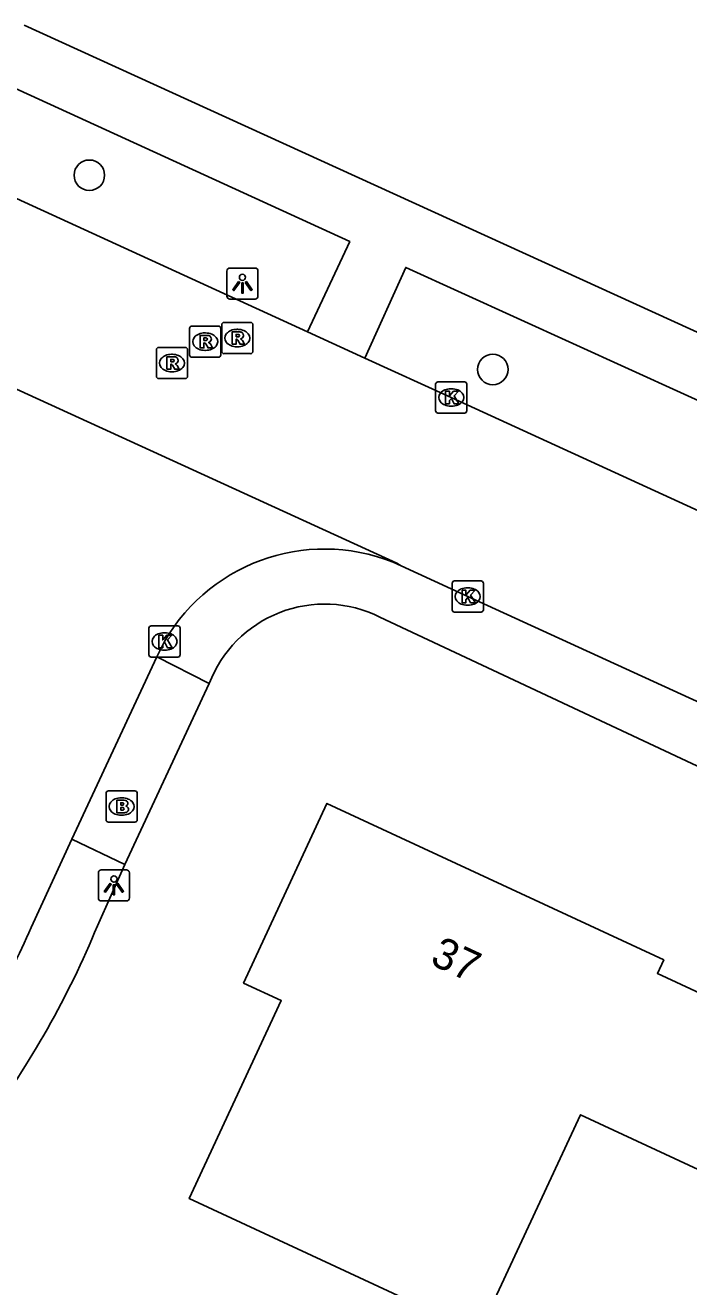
# Model space of a CAD drawing. Extents: x 162722 to 165099, y 384721 to 386283.
# Drawn here: x 164039.98 to 164061.27, y 385139.03 to 385179.48 of the extents above; entities that cross this region are included whole.
import ezdxf

# ---------------------------------------------------------------- set-up
doc = ezdxf.new("R2010")
doc.units = 0
for name, color, linetype in [('IMGEO_Boom', 7, 'Continuous'), ('IMGEO_Brandkraan', 7, 'Continuous'), ('IMGEO_Kolk', 7, 'Continuous'), ('IMGEO_Lichtpunt', 7, 'Continuous'), ('IMGEO_Pand', 7, 'Continuous'), ('IMGEO_Pand_nummerreeks', 7, 'Continuous'), ('IMGEO_Parkeervlak_open', 7, 'Continuous'), ('IMGEO_Rijbaan_lokaal_gesloten', 7, 'Continuous'), ('IMGEO_Rioolput', 7, 'Continuous'), ('IMGEO_Voetpad_open', 7, 'Continuous')]:
    doc.layers.add(name, color=color, linetype=linetype)

msp = doc.modelspace()

# ---------------------------------------------------------------- linework, layer by layer
at = {"layer": 'IMGEO_Boom'}
for centre in [(164042.041, 385174.672), (164054.98, 385168.446)]:
    msp.add_circle(centre, 0.489, dxfattribs=at)
at = {"layer": 'IMGEO_Brandkraan'}
for p, q in [((164042.576, 385154.006), (164042.576, 385154.858)), ((164042.651, 385154.932), (164043.503, 385154.932)), ((164043.577, 385154.858), (164043.577, 385154.006)), ((164043.064, 385154.712), (164043.089, 385154.712)), ((164043.503, 385153.932), (164042.651, 385153.932)), ((164043.087, 385154.152), (164043.062, 385154.152))]:
    msp.add_line(p, q, dxfattribs=at)
for points in [[(164042.576, 385154.006), (164042.576, 385154.858)], [(164042.651, 385154.932), (164043.503, 385154.932)], [(164043.577, 385154.858), (164043.577, 385154.006)], [(164042.924, 385154.632), (164042.924, 385154.232), (164043.137, 385154.232)], [(164043.155, 385154.632), (164042.924, 385154.632)], [(164043.103, 385154.551), (164043.049, 385154.551), (164043.049, 385154.475)], [(164043.049, 385154.475), (164043.102, 385154.475)], [(164043.111, 385154.399), (164043.049, 385154.399), (164043.049, 385154.318)], [(164043.503, 385153.932), (164042.651, 385153.932)], [(164043.049, 385154.318), (164043.111, 385154.318)]]:
    msp.add_lwpolyline(points, dxfattribs=at)
for centre, radius, start, end in [((164042.653, 385154.856), 0.0765, 91.552, 178.448), ((164042.653, 385154.856), 0.0765, 91.552, 178.448), ((164043.501, 385154.856), 0.0765, 1.552, 88.448), ((164043.501, 385154.856), 0.0765, 1.552, 88.448), ((164043.104, 385154.513), 0.0379, 267.8285, 90.9355), ((164043.112, 385154.358), 0.0404, 269.8759, 90.5077), ((164043.159, 385154.487), 0.145, 59.4692, 91.5367), ((164043.184, 385154.534), 0.0922, 285.5137, 58.1501), ((164043.189, 385154.342), 0.105, 301.3115, 78.989), ((164042.653, 385154.008), 0.0765, 181.552, 268.448), ((164042.653, 385154.008), 0.0765, 181.552, 268.448), ((164043.143, 385154.483), 0.251, 268.6676, 293.5347), ((164043.501, 385154.008), 0.0765, 271.552, 358.448), ((164043.501, 385154.008), 0.0765, 271.552, 358.448)]:
    msp.add_arc(centre, radius, start, end, dxfattribs=at)
for centre, major_axis, ratio, start_param, end_param in [((164043.063, 385154.432), (-0.387, 0.002), 0.722429, 4.712389, 7.853982), ((164043.088, 385154.432), (-0.39, 0.002), 0.717154, 1.570796, 4.712389)]:
    msp.add_ellipse(centre, major_axis=major_axis, ratio=ratio, start_param=start_param, end_param=end_param, dxfattribs=at)
at = {"layer": 'IMGEO_Kolk'}
for p, q in [((164053.147, 385167.122), (164053.147, 385167.974)), ((164053.222, 385168.048), (164054.074, 385168.048)), ((164053.635, 385167.828), (164053.66, 385167.828)), ((164054.148, 385167.974), (164054.148, 385167.122)), ((164054.074, 385167.048), (164053.222, 385167.048)), ((164053.658, 385167.268), (164053.633, 385167.268)), ((164053.751, 385161.665), (164054.603, 385161.665)), ((164053.676, 385160.739), (164053.676, 385161.591)), ((164054.164, 385161.445), (164054.189, 385161.445)), ((164054.677, 385161.591), (164054.677, 385160.739)), ((164054.187, 385160.885), (164054.162, 385160.885)), ((164054.603, 385160.665), (164053.751, 385160.665)), ((164043.951, 385159.299), (164043.951, 385160.151)), ((164044.026, 385160.225), (164044.878, 385160.225)), ((164044.439, 385160.005), (164044.464, 385160.005)), ((164044.952, 385160.151), (164044.952, 385159.299)), ((164044.878, 385159.225), (164044.026, 385159.225)), ((164044.462, 385159.445), (164044.437, 385159.445))]:
    msp.add_line(p, q, dxfattribs=at)
for points in [[(164053.147, 385167.122), (164053.147, 385167.974)], [(164053.222, 385168.048), (164054.074, 385168.048)], [(164053.468, 385167.748), (164053.591, 385167.748), (164053.591, 385167.597), (164053.721, 385167.748), (164053.885, 385167.748), (164053.739, 385167.597), (164053.892, 385167.348), (164053.74, 385167.348), (164053.655, 385167.512), (164053.591, 385167.445), (164053.591, 385167.348), (164053.468, 385167.348), (164053.468, 385167.748)], [(164054.148, 385167.974), (164054.148, 385167.122)], [(164054.074, 385167.048), (164053.222, 385167.048)], [(164053.751, 385161.665), (164054.603, 385161.665)], [(164053.676, 385160.739), (164053.676, 385161.591)], [(164053.997, 385161.365), (164054.12, 385161.365), (164054.12, 385161.214), (164054.25, 385161.365), (164054.414, 385161.365), (164054.268, 385161.214), (164054.421, 385160.965), (164054.269, 385160.965), (164054.184, 385161.129), (164054.12, 385161.062), (164054.12, 385160.965), (164053.997, 385160.965), (164053.997, 385161.365)], [(164054.677, 385161.591), (164054.677, 385160.739)], [(164054.603, 385160.665), (164053.751, 385160.665)], [(164043.951, 385159.299), (164043.951, 385160.151)], [(164044.026, 385160.225), (164044.878, 385160.225)], [(164044.952, 385160.151), (164044.952, 385159.299)], [(164044.272, 385159.925), (164044.395, 385159.925), (164044.395, 385159.774), (164044.525, 385159.925), (164044.689, 385159.925), (164044.543, 385159.774), (164044.696, 385159.525), (164044.544, 385159.525), (164044.459, 385159.689), (164044.395, 385159.622), (164044.395, 385159.525), (164044.272, 385159.525), (164044.272, 385159.925)], [(164044.878, 385159.225), (164044.026, 385159.225)]]:
    msp.add_lwpolyline(points, dxfattribs=at)
for centre, start, end in [((164053.224, 385167.972), 91.552, 178.448), ((164053.224, 385167.972), 91.552, 178.448), ((164054.072, 385167.972), 1.552, 88.448), ((164054.072, 385167.972), 1.552, 88.448), ((164053.224, 385167.124), 181.552, 268.448), ((164053.224, 385167.124), 181.552, 268.448), ((164054.072, 385167.124), 271.552, 358.448), ((164054.072, 385167.124), 271.552, 358.448), ((164053.753, 385161.589), 91.552, 178.448), ((164053.753, 385161.589), 91.552, 178.448), ((164054.601, 385161.589), 1.552, 88.448), ((164054.601, 385161.589), 1.552, 88.448), ((164053.753, 385160.741), 181.552, 268.448), ((164053.753, 385160.741), 181.552, 268.448), ((164054.601, 385160.741), 271.552, 358.448), ((164054.601, 385160.741), 271.552, 358.448), ((164044.028, 385160.149), 91.552, 178.448), ((164044.028, 385160.149), 91.552, 178.448), ((164044.876, 385160.149), 1.552, 88.448), ((164044.876, 385160.149), 1.552, 88.448), ((164044.028, 385159.301), 181.552, 268.448), ((164044.028, 385159.301), 181.552, 268.448), ((164044.876, 385159.301), 271.552, 358.448), ((164044.876, 385159.301), 271.552, 358.448)]:
    msp.add_arc(centre, 0.0765, start, end, dxfattribs=at)
for centre, major_axis, ratio, start_param, end_param in [((164053.634, 385167.548), (-0.387, 0.002), 0.722429, 4.712389, 7.853982), ((164053.659, 385167.548), (-0.39, 0.002), 0.717154, 1.570796, 4.712389), ((164054.163, 385161.165), (-0.387, 0.002), 0.722429, 4.712389, 7.853982), ((164054.188, 385161.165), (-0.39, 0.002), 0.717154, 1.570796, 4.712389), ((164044.438, 385159.725), (-0.387, 0.002), 0.722429, 4.712389, 7.853982), ((164044.463, 385159.725), (-0.39, 0.002), 0.717154, 1.570796, 4.712389)]:
    msp.add_ellipse(centre, major_axis=major_axis, ratio=ratio, start_param=start_param, end_param=end_param, dxfattribs=at)
at = {"layer": 'IMGEO_Lichtpunt'}
for p, q in [((164046.452, 385171.602), (164046.452, 385170.795)), ((164046.452, 385171.602), (164046.452, 385170.795)), ((164047.354, 385171.697), (164046.546, 385171.697)), ((164047.354, 385171.697), (164046.546, 385171.697)), ((164047.448, 385170.795), (164047.448, 385171.602)), ((164047.448, 385170.795), (164047.448, 385171.602)), ((164046.546, 385170.701), (164047.354, 385170.701)), ((164046.546, 385170.701), (164047.354, 385170.701)), ((164042.329, 385152.308), (164042.329, 385151.501)), ((164042.329, 385152.308), (164042.329, 385151.501)), ((164043.231, 385152.403), (164042.423, 385152.403)), ((164043.231, 385152.403), (164042.423, 385152.403)), ((164043.325, 385151.501), (164043.325, 385152.308)), ((164043.325, 385151.501), (164043.325, 385152.308)), ((164042.423, 385151.407), (164043.231, 385151.407)), ((164042.423, 385151.407), (164043.231, 385151.407))]:
    msp.add_line(p, q, dxfattribs=at)
for points in [[(164046.826, 385171.266), (164046.865, 385171.238), (164046.677, 385170.976), (164046.639, 385171.003), (164046.826, 385171.266)], [(164046.928, 385171.218), (164046.975, 385171.218), (164046.975, 385170.896), (164046.928, 385170.896), (164046.928, 385171.218)], [(164047.038, 385171.238), (164047.076, 385171.265), (164047.263, 385171.003), (164047.224, 385170.975), (164047.038, 385171.238)], [(164042.703, 385151.972), (164042.742, 385151.944), (164042.554, 385151.682), (164042.516, 385151.709), (164042.703, 385151.972)], [(164042.805, 385151.924), (164042.852, 385151.924), (164042.852, 385151.602), (164042.805, 385151.602), (164042.805, 385151.924)], [(164042.915, 385151.944), (164042.953, 385151.971), (164043.14, 385151.709), (164043.101, 385151.681), (164042.915, 385151.944)]]:
    msp.add_lwpolyline(points, dxfattribs=at)
for centre in [(164046.951, 385171.4), (164042.828, 385152.106)]:
    msp.add_circle(centre, 0.0994, dxfattribs=at)
for centre, start, end in [((164046.546, 385171.602), 90, 180), ((164046.546, 385171.602), 90, 180), ((164047.354, 385171.602), 0, 90), ((164047.354, 385171.602), 0, 90), ((164046.546, 385170.795), 180, 270), ((164046.546, 385170.795), 180, 270), ((164047.354, 385170.795), 270, 0), ((164047.354, 385170.795), 270, 360), ((164042.423, 385152.308), 90, 180), ((164042.423, 385152.308), 90, 180), ((164043.231, 385152.308), 0, 90), ((164043.231, 385152.308), 0, 90), ((164042.423, 385151.501), 180, 270), ((164042.423, 385151.501), 180, 270), ((164043.231, 385151.501), 270, 0), ((164043.231, 385151.501), 270, 360)]:
    msp.add_arc(centre, 0.0946, start, end, dxfattribs=at)
at = {"layer": 'IMGEO_Pand'}
msp.add_lwpolyline([(164049.78, 385139.755), (164045.245, 385141.862), (164048.193, 385148.208), (164046.985, 385148.769), (164049.662, 385154.531), (164060.462, 385149.513), (164060.262, 385149.081), (164069.933, 385144.587), (164067.827, 385140.053), (164067.763, 385139.916), (164057.79, 385144.549), (164054.536, 385137.545), (164049.78, 385139.755)], dxfattribs=at)
at = {"layer": 'IMGEO_Parkeervlak_open'}
msp.add_lwpolyline([(164065.329, 385153.951), (164051.353, 385160.508)], dxfattribs=at)
msp.add_arc((164049.586, 385156.962), 3.962, 63.5124, 159.119, dxfattribs=at)
at = {"layer": 'IMGEO_Rijbaan_lokaal_gesloten'}
for points in [[(164049.034, 385169.655), (164038.924, 385174.279), (164037.91, 385174.757)], [(164050.878, 385168.812), (164049.034, 385169.655)], [(164052.042, 385162.153), (164051.9, 385162.23), (164036.795, 385169.137)], [(164070.499, 385159.839), (164069.537, 385160.271), (164053.648, 385167.548), (164050.878, 385168.812)], [(164052.042, 385162.153), (164054.177, 385161.165), (164066.085, 385155.714)], [(164044.201, 385159.231), (164044.452, 385159.725)], [(164041.473, 385153.384), (164044.201, 385159.231)], [(164040.174, 385150.554), (164041.473, 385153.384)]]:
    msp.add_lwpolyline(points, dxfattribs=at)
for centre, radius, start, end in [((164049.581, 385156.768), 5.92, 65.4408, 150.0376), ((164016.372, 385160.925), 25.963, 323.5972, 336.4559)]:
    msp.add_arc(centre, radius, start, end, dxfattribs=at)
at = {"layer": 'IMGEO_Rioolput'}
for p, q in [((164045.256, 385168.911), (164045.256, 385169.763)), ((164045.331, 385169.837), (164046.183, 385169.837)), ((164046.257, 385169.763), (164046.257, 385168.911)), ((164046.285, 385169.026), (164046.285, 385169.878)), ((164046.36, 385169.952), (164047.212, 385169.952)), ((164046.773, 385169.732), (164046.798, 385169.732)), ((164047.286, 385169.878), (164047.286, 385169.026)), ((164045.744, 385169.617), (164045.769, 385169.617)), ((164044.189, 385168.225), (164044.189, 385169.077)), ((164044.264, 385169.151), (164045.116, 385169.151)), ((164044.677, 385168.931), (164044.702, 385168.931)), ((164045.19, 385169.077), (164045.19, 385168.225)), ((164045.767, 385169.057), (164045.742, 385169.057)), ((164047.212, 385168.952), (164046.36, 385168.952)), ((164046.796, 385169.172), (164046.771, 385169.172)), ((164046.183, 385168.837), (164045.331, 385168.837)), ((164045.116, 385168.151), (164044.264, 385168.151)), ((164044.7, 385168.371), (164044.675, 385168.371))]:
    msp.add_line(p, q, dxfattribs=at)
for points in [[(164045.256, 385168.911), (164045.256, 385169.763)], [(164045.331, 385169.837), (164046.183, 385169.837)], [(164046.257, 385169.763), (164046.257, 385168.911)], [(164046.285, 385169.026), (164046.285, 385169.878)], [(164046.36, 385169.952), (164047.212, 385169.952)], [(164047.286, 385169.878), (164047.286, 385169.026)], [(164045.845, 385169.535), (164045.593, 385169.537), (164045.593, 385169.137)], [(164045.593, 385169.137), (164045.717, 385169.137), (164045.717, 385169.299), (164045.728, 385169.299)], [(164045.771, 385169.456), (164045.717, 385169.456), (164045.717, 385169.375)], [(164045.717, 385169.375), (164045.769, 385169.375)], [(164046.874, 385169.65), (164046.622, 385169.652), (164046.622, 385169.252)], [(164046.622, 385169.252), (164046.746, 385169.252), (164046.746, 385169.414), (164046.757, 385169.414)], [(164046.8, 385169.571), (164046.746, 385169.571), (164046.746, 385169.49)], [(164046.746, 385169.49), (164046.798, 385169.49)], [(164046.804, 385169.385), (164046.875, 385169.252), (164047.015, 385169.252), (164046.95, 385169.378)], [(164044.189, 385168.225), (164044.189, 385169.077)], [(164044.264, 385169.151), (164045.116, 385169.151)], [(164045.19, 385169.077), (164045.19, 385168.225)], [(164045.775, 385169.27), (164045.846, 385169.137), (164045.986, 385169.137), (164045.921, 385169.263)], [(164047.212, 385168.952), (164046.36, 385168.952)], [(164044.778, 385168.849), (164044.526, 385168.851), (164044.526, 385168.451)], [(164044.526, 385168.451), (164044.65, 385168.451), (164044.65, 385168.613), (164044.661, 385168.613)], [(164044.704, 385168.77), (164044.65, 385168.77), (164044.65, 385168.689)], [(164044.65, 385168.689), (164044.702, 385168.689)], [(164044.708, 385168.584), (164044.779, 385168.451), (164044.919, 385168.451), (164044.854, 385168.577)], [(164046.183, 385168.837), (164045.331, 385168.837)], [(164045.116, 385168.151), (164044.264, 385168.151)]]:
    msp.add_lwpolyline(points, dxfattribs=at)
for centre, radius, start, end in [((164045.333, 385169.761), 0.0765, 91.552, 178.448), ((164045.333, 385169.761), 0.0765, 91.552, 178.448), ((164046.181, 385169.761), 0.0765, 1.552, 88.448), ((164046.181, 385169.761), 0.0765, 1.552, 88.448), ((164046.362, 385169.876), 0.0765, 91.552, 178.448), ((164046.362, 385169.876), 0.0765, 91.552, 178.448), ((164047.21, 385169.876), 0.0765, 1.552, 88.448), ((164047.21, 385169.876), 0.0765, 1.552, 88.448), ((164045.727, 385169.246), 0.0533, 26.0293, 88.6989), ((164045.753, 385169.564), 0.19, 274.7715, 282.9687), ((164045.777, 385169.36), 0.0964, 77.0061, 93.1865), ((164045.791, 385169.417), 0.0378, 276.6634, 79.6772), ((164045.844, 385169.425), 0.109, 350.3612, 89.416), ((164045.842, 385169.425), 0.112, 277.5842, 350.9817), ((164045.826, 385169.21), 0.108, 29.5134, 73.7905), ((164046.756, 385169.361), 0.0533, 26.0293, 88.6989), ((164046.782, 385169.679), 0.19, 274.7715, 282.9687), ((164046.806, 385169.475), 0.0964, 77.0061, 93.1865), ((164046.82, 385169.532), 0.0378, 276.6634, 79.6772), ((164046.873, 385169.54), 0.109, 350.3612, 89.416), ((164046.871, 385169.54), 0.112, 277.5842, 350.9817), ((164046.855, 385169.325), 0.108, 29.5134, 73.7905), ((164044.266, 385169.075), 0.0765, 91.552, 178.448), ((164044.266, 385169.075), 0.0765, 91.552, 178.448), ((164045.114, 385169.075), 0.0765, 1.552, 88.448), ((164045.114, 385169.075), 0.0765, 1.552, 88.448), ((164045.333, 385168.913), 0.0765, 181.552, 268.448), ((164045.333, 385168.913), 0.0765, 181.552, 268.448), ((164046.181, 385168.913), 0.0765, 271.552, 358.448), ((164046.181, 385168.913), 0.0765, 271.552, 358.448), ((164046.362, 385169.028), 0.0765, 181.552, 268.448), ((164046.362, 385169.028), 0.0765, 181.552, 268.448), ((164047.21, 385169.028), 0.0765, 271.552, 358.448), ((164047.21, 385169.028), 0.0765, 271.552, 358.448), ((164044.66, 385168.56), 0.0533, 26.0293, 88.6989), ((164044.686, 385168.878), 0.19, 274.7715, 282.9687), ((164044.71, 385168.674), 0.0964, 77.0061, 93.1865), ((164044.724, 385168.731), 0.0378, 276.6634, 79.6772), ((164044.777, 385168.739), 0.109, 350.3612, 89.416), ((164044.775, 385168.739), 0.112, 277.5842, 350.9817), ((164044.759, 385168.524), 0.108, 29.5134, 73.7905), ((164044.266, 385168.227), 0.0765, 181.552, 268.448), ((164044.266, 385168.227), 0.0765, 181.552, 268.448), ((164045.114, 385168.227), 0.0765, 271.552, 358.448), ((164045.114, 385168.227), 0.0765, 271.552, 358.448)]:
    msp.add_arc(centre, radius, start, end, dxfattribs=at)
for centre, major_axis, ratio, start_param, end_param in [((164046.772, 385169.452), (-0.387, 0.002), 0.722429, 4.712389, 7.853982), ((164046.797, 385169.452), (-0.39, 0.002), 0.717154, 1.570796, 4.712389), ((164045.743, 385169.337), (-0.387, 0.002), 0.722429, 4.712389, 7.853982), ((164045.768, 385169.337), (-0.39, 0.002), 0.717154, 1.570796, 4.712389), ((164044.676, 385168.651), (-0.387, 0.002), 0.722429, 4.712389, 7.853982), ((164044.701, 385168.651), (-0.39, 0.002), 0.717154, 1.570796, 4.712389)]:
    msp.add_ellipse(centre, major_axis=major_axis, ratio=ratio, start_param=start_param, end_param=end_param, dxfattribs=at)
at = {"layer": 'IMGEO_Voetpad_open'}
for points in [[(164039.945, 385179.482), (164072.64, 385164.57)], [(164039.144, 385177.688), (164050.39, 385172.544), (164049.034, 385169.655)], [(164050.878, 385168.812), (164052.189, 385171.716), (164071.832, 385162.783)], [(164044.201, 385159.231), (164045.884, 385158.374)], [(164045.884, 385158.374), (164043.183, 385152.572)], [(164043.183, 385152.572), (164041.473, 385153.384)], [(164043.183, 385152.572), (164042.299, 385150.607)]]:
    msp.add_lwpolyline(points, dxfattribs=at)
msp.add_arc((164015.003, 385161.83), 29.513, 323.3909, 337.649, dxfattribs=at)

# ---------------------------------------------------------------- texts
at = {"layer": 'IMGEO_Pand_nummerreeks'}
msp.add_text('37', height=1, rotation=335.079, dxfattribs=at).set_placement((164052.93, 385149.395))

doc.saveas('drawing.dxf')
